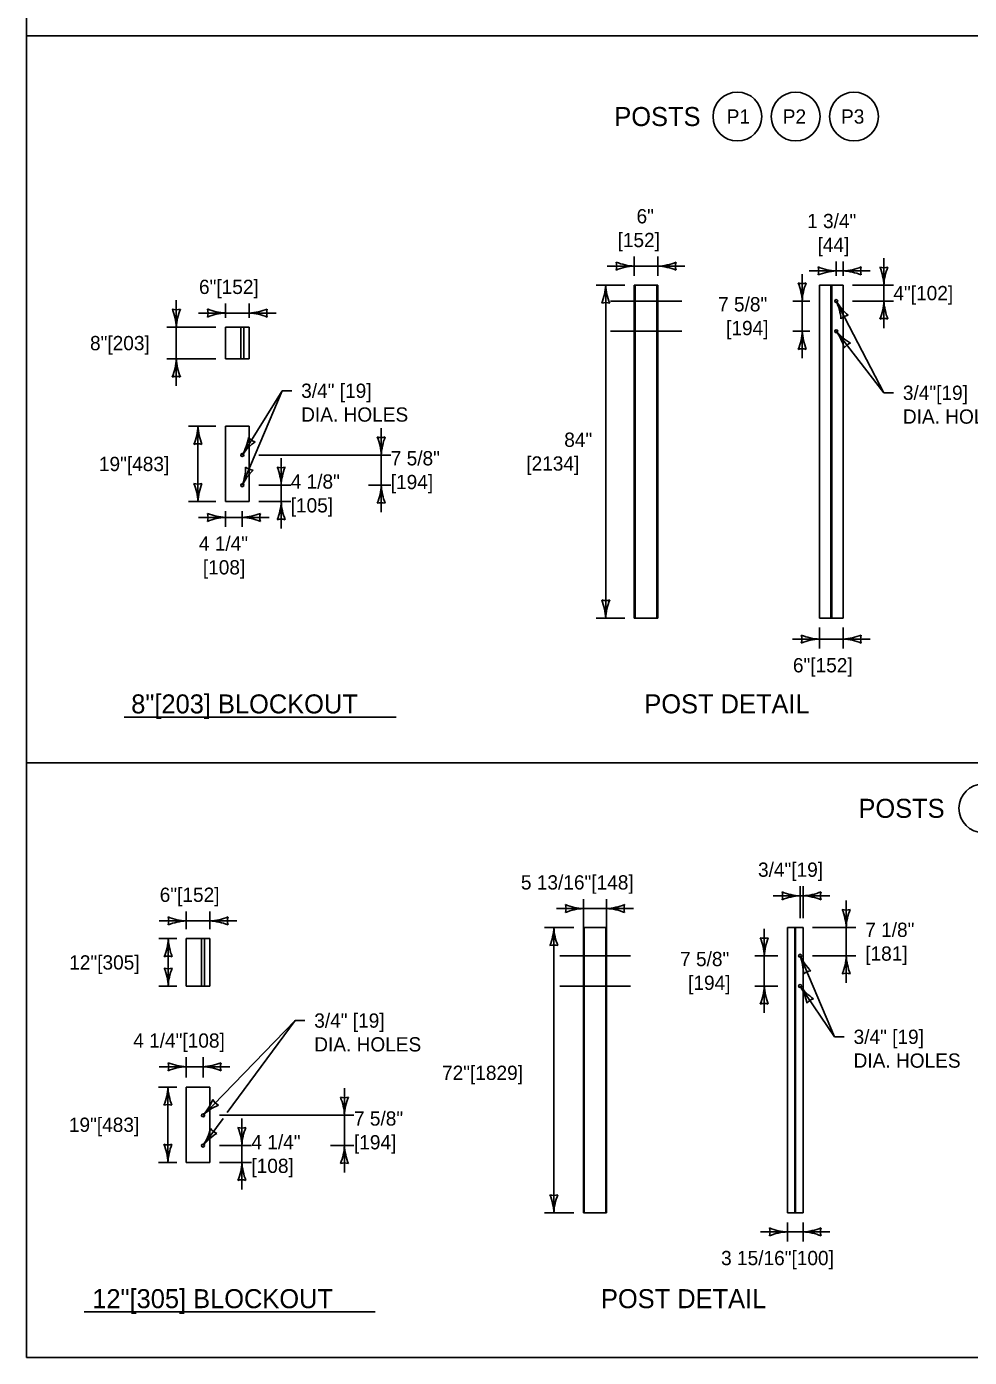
# Model space of a CAD drawing. Extents: x 49991 to 50160, y 49948 to 50051.
# Drawn here: x 49999.38 to 50003.35, y 49987.8 to 49993.4 of the extents above; entities that cross this region are included whole.
import ezdxf

# ---------------------------------------------------------------- set-up
doc = ezdxf.new("R2010")
doc.units = 0
for name, color, linetype in [('Level 1', 7, 'Continuous'), ('Level 2', 7, 'Continuous'), ('Level 3', 7, 'Continuous'), ('Level 4', 7, 'Continuous'), ('Level 5', 7, 'Continuous')]:
    doc.layers.add(name, color=color, linetype=linetype)

msp = doc.modelspace()

# ---------------------------------------------------------------- linework, layer by layer
at = {"layer": 'Level 1'}
for p, q in [((50001.9407, 49990.9086), (50001.9407, 49992.3086)), ((50001.9407, 49992.3086), (50002.0407, 49992.3086)), ((50001.9451, 49990.9086), (50001.9451, 49992.3086)), ((50002.0364, 49990.9086), (50002.0364, 49992.3086)), ((50002.0407, 49990.9086), (50002.0407, 49992.3086)), ((50002.7199, 49990.9086), (50002.7199, 49992.3086)), ((50002.7199, 49992.3086), (50002.8199, 49992.3086)), ((50002.8199, 49990.9086), (50002.8199, 49992.3086)), ((50000.3204, 49992.1316), (50000.2204, 49992.1316)), ((50000.2204, 49991.9983), (50000.2204, 49992.1316)), ((50000.3204, 49991.9983), (50000.3204, 49992.1316)), ((50000.3204, 49991.9983), (50000.2204, 49991.9983)), ((50000.2204, 49991.3984), (50000.2204, 49991.7151)), ((50000.2204, 49991.7151), (50000.3204, 49991.7151)), ((50000.3204, 49991.3984), (50000.3204, 49991.7151)), ((50000.2204, 49991.3984), (50000.3204, 49991.3984)), ((50002.0407, 49990.9086), (50001.9407, 49990.9086)), ((50002.8199, 49990.9086), (50002.7199, 49990.9086)), ((49999.3835, 49990.2991), (50008.2653, 49990.2991)), ((50000.1551, 49989.56), (50000.0551, 49989.56)), ((50000.0551, 49989.56), (50000.0551, 49989.36)), ((50000.1551, 49989.36), (50000.1551, 49989.56)), ((50001.7272, 49989.6067), (50001.7272, 49988.4067)), ((50001.7272, 49989.6067), (50001.8244, 49989.6067)), ((50001.7305, 49989.6067), (50001.7305, 49988.4067)), ((50001.8212, 49989.6067), (50001.8212, 49988.4067)), ((50001.8244, 49989.6067), (50001.8244, 49988.4067)), ((50002.5855, 49989.6067), (50002.6512, 49989.6067)), ((50002.5855, 49989.6067), (50002.5855, 49988.4067)), ((50002.6512, 49989.6067), (50002.6512, 49988.4067)), ((50000.1551, 49989.36), (50000.0551, 49989.36)), ((50000.0551, 49988.619), (50000.0551, 49988.9356)), ((50000.0551, 49988.9356), (50000.1551, 49988.9356)), ((50000.1551, 49988.619), (50000.1551, 49988.9356)), ((50000.0551, 49988.619), (50000.1551, 49988.619)), ((50001.7272, 49988.4067), (50001.8244, 49988.4067)), ((50002.6512, 49988.4067), (50002.5855, 49988.4067))]:
    msp.add_line(p, q, dxfattribs=at)
msp.add_lwpolyline([(49999.3835, 49998.9992), (50016.7501, 49998.9992), (50016.7501, 49987.7988), (49999.3835, 49987.7988)], close=True, dxfattribs=at)
msp.add_lwpolyline([(50006.474, 49990.2991), (50006.474, 49993.358), (49999.3835, 49993.358)], dxfattribs=at)
for centre in [(50002.7908, 49992.2419), (50002.7908, 49992.1149), (50000.2913, 49991.5943), (50000.2913, 49991.4672), (50002.6387, 49989.488), (50002.6387, 49989.3609), (50000.1259, 49988.8169), (50000.126, 49988.6898)]:
    msp.add_circle(centre, 0.00625, dxfattribs=at)
at = {"layer": 'Level 2'}
for p, q in [((49999.7939, 49990.4914), (50000.9385, 49990.4914)), ((49999.6258, 49987.9898), (50000.8504, 49987.9898))]:
    msp.add_line(p, q, dxfattribs=at)
for centre in [(50002.3749, 49993.018), (50002.6202, 49993.018), (50002.8655, 49993.018), (50003.4096, 49990.1082)]:
    msp.add_circle(centre, 0.1026, dxfattribs=at)
at = {"layer": 'Level 3'}
for p, q in [((50001.9407, 49992.3486), (50001.9407, 49992.4286)), ((50002.0407, 49992.3486), (50002.0407, 49992.4286)), ((50002.7908, 49992.3486), (50002.7908, 49992.4086)), ((50002.8199, 49992.3486), (50002.8199, 49992.4086)), ((50002.9914, 49992.422), (50002.9914, 49992.1285)), ((50001.8273, 49992.3886), (50002.1542, 49992.3886)), ((50002.6478, 49992.0014), (50002.6478, 49992.3554)), ((50002.6773, 49992.3686), (50002.9334, 49992.3686)), ((50001.9007, 49992.3086), (50001.7807, 49992.3086)), ((50001.8207, 49992.3086), (50001.8207, 49990.9086)), ((50002.8599, 49992.3086), (50003.0314, 49992.3086)), ((50000.0136, 49991.8849), (50000.0136, 49992.2451)), ((50002.6799, 49992.2419), (50002.6078, 49992.2419)), ((50002.7908, 49992.2419), (50002.9913, 49991.8561)), ((50002.8599, 49992.2419), (50003.0314, 49992.2419)), ((50000.107, 49992.1916), (50000.4339, 49992.1916)), ((50000.2204, 49992.1716), (50000.2204, 49992.2316)), ((50000.3204, 49992.1716), (50000.3204, 49992.2316)), ((50000.1804, 49992.1316), (49999.9736, 49992.1316)), ((50002.6799, 49992.1149), (50002.6078, 49992.1149)), ((50002.7908, 49992.1149), (50002.9913, 49991.8561)), ((50000.1804, 49991.9983), (49999.9736, 49991.9983)), ((50000.2913, 49991.4672), (50000.4591, 49991.8646)), ((50000.2913, 49991.5943), (50000.4591, 49991.8646)), ((50000.4591, 49991.8646), (50000.4991, 49991.8646)), ((50002.9913, 49991.8561), (50003.0313, 49991.8561)), ((50000.1804, 49991.7151), (50000.0646, 49991.7151)), ((50000.1046, 49991.7151), (50000.1046, 49991.3984)), ((50000.876, 49991.7077), (50000.876, 49991.3537)), ((50000.3604, 49991.5942), (50000.916, 49991.5942)), ((50000.4549, 49991.5806), (50000.4549, 49991.285)), ((50000.3604, 49991.4672), (50000.4949, 49991.4672)), ((50000.8217, 49991.4672), (50000.916, 49991.4672)), ((50000.1804, 49991.3984), (50000.0646, 49991.3984)), ((50000.3604, 49991.3984), (50000.4949, 49991.3984)), ((50000.2204, 49991.3584), (50000.2204, 49991.292)), ((50000.2913, 49991.3584), (50000.2913, 49991.292)), ((50000.107, 49991.332), (50000.4047, 49991.332)), ((50000.4549, 49991.3226), (50000.4549, 49991.3027)), ((50001.9007, 49990.9086), (50001.7807, 49990.9086)), ((50002.7199, 49990.8686), (50002.7199, 49990.7801)), ((50002.8199, 49990.8686), (50002.8199, 49990.7801)), ((50002.6065, 49990.8201), (50002.9334, 49990.8201)), ((50002.6387, 49989.6467), (50002.6387, 49989.7802)), ((50002.6512, 49989.6467), (50002.6512, 49989.7802)), ((50001.7272, 49989.6467), (50001.7272, 49989.7267)), ((50001.8244, 49989.6467), (50001.8244, 49989.7267)), ((50002.5253, 49989.7402), (50002.7646, 49989.7402)), ((50002.8329, 49989.7201), (50002.8329, 49989.3745)), ((50000.0551, 49989.6), (50000.0551, 49989.6747)), ((50000.1551, 49989.6), (50000.1551, 49989.6747)), ((50001.6138, 49989.6867), (50001.9378, 49989.6867)), ((50000.2686, 49989.6347), (49999.9417, 49989.6347)), ((50001.7272, 49989.6067), (50001.7272, 49989.6467)), ((50001.8244, 49989.6067), (50001.8244, 49989.6467)), ((50000.0151, 49989.56), (49999.9396, 49989.56)), ((49999.9796, 49989.56), (49999.9796, 49989.36)), ((50001.6872, 49989.6067), (50001.5624, 49989.6067)), ((50001.6024, 49989.6067), (50001.6024, 49988.4067)), ((50002.4879, 49989.2474), (50002.4879, 49989.6014)), ((50002.6912, 49989.6067), (50002.8729, 49989.6067)), ((50002.5455, 49989.488), (50002.4479, 49989.488)), ((50002.6387, 49989.488), (50002.7839, 49989.1472)), ((50002.6912, 49989.488), (50002.8729, 49989.488)), ((50000.0151, 49989.36), (49999.9396, 49989.36)), ((50002.5455, 49989.3609), (50002.4479, 49989.3609)), ((50002.6387, 49989.3609), (50002.7839, 49989.1472)), ((50000.1259, 49988.8169), (50000.514, 49989.2155)), ((50000.2281, 49988.8282), (50000.514, 49989.2155)), ((50000.514, 49989.2155), (50000.554, 49989.2155)), ((50002.7839, 49989.1472), (50002.8239, 49989.1472)), ((50000.0551, 49988.9756), (50000.0551, 49989.0615)), ((50000.1259, 49988.9756), (50000.1259, 49989.0615)), ((49999.9417, 49989.0215), (50000.2394, 49989.0215)), ((50000.0151, 49988.9356), (49999.9382, 49988.9356)), ((49999.9782, 49988.9356), (49999.9782, 49988.619)), ((50000.7212, 49988.9306), (50000.7212, 49988.5766)), ((50000.126, 49988.6898), (50000.2104, 49988.8042)), ((50000.1951, 49988.8171), (50000.7612, 49988.8171)), ((50000.2896, 49988.8035), (50000.2896, 49988.5055)), ((50000.1951, 49988.69), (50000.3296, 49988.69)), ((50000.6619, 49988.69), (50000.7612, 49988.69)), ((50000.0151, 49988.619), (49999.9382, 49988.619)), ((50000.1951, 49988.619), (50000.3296, 49988.619)), ((50000.2896, 49988.5455), (50000.2896, 49988.5055)), ((50001.6872, 49988.4067), (50001.5624, 49988.4067)), ((50002.4721, 49988.3267), (50002.7646, 49988.3267)), ((50002.5855, 49988.3667), (50002.5855, 49988.2867)), ((50002.6512, 49988.3667), (50002.6512, 49988.2867))]:
    msp.add_line(p, q, dxfattribs=at)
for centre, radius, start, end in [((50001.9499, 49992.6111), 0.2223, 247.456, 267.6395), ((50001.8125, 49992.389), 0.0548, 342.1388, 17.8612), ((50001.9522, 49992.1563), 0.233, 92.8273, 112.0772), ((50002.0292, 49992.6213), 0.233, 272.8273, 292.0772), ((50002.0316, 49992.1665), 0.2223, 67.456, 87.6395), ((50002.1689, 49992.3886), 0.0548, 162.1388, 197.8612), ((50002.7999, 49992.5907), 0.2223, 247.456, 267.6395), ((50002.6626, 49992.3686), 0.0548, 342.1388, 17.8612), ((50002.8023, 49992.1359), 0.233, 92.8273, 112.0772), ((50002.8084, 49992.6013), 0.233, 272.8273, 292.0772), ((50002.8108, 49992.1465), 0.2223, 67.456, 87.6395), ((50002.9482, 49992.3686), 0.0548, 162.1388, 197.8612), ((50002.9914, 49992.4368), 0.0548, 252.1388, 287.8612), ((50002.7587, 49992.2971), 0.233, 2.8273, 22.0772), ((50003.2136, 49992.2994), 0.2223, 157.456, 177.6395), ((50001.5986, 49992.3178), 0.2223, 337.456, 357.6395), ((50002.0534, 49992.3201), 0.233, 182.8273, 202.0772), ((50002.6478, 49992.3702), 0.0548, 252.1388, 287.8612), ((50002.415, 49992.2304), 0.233, 2.8273, 22.0772), ((50002.8699, 49992.2328), 0.2223, 157.456, 177.6395), ((50002.5894, 49992.1476), 0.2223, 4.9176, 25.1011), ((50002.992, 49992.3595), 0.233, 210.2889, 229.5388), ((50002.7693, 49992.2511), 0.2223, 337.456, 357.6395), ((50003.2241, 49992.2534), 0.233, 182.8273, 202.0772), ((50000.0136, 49992.2599), 0.0548, 252.1388, 287.8612), ((49999.7809, 49992.1201), 0.233, 2.8273, 22.0772), ((50000.2358, 49992.1225), 0.2223, 157.456, 177.6395), ((50000.2296, 49992.4138), 0.2223, 247.456, 267.6395), ((50000.0922, 49992.1916), 0.0548, 342.1388, 17.8612), ((50000.2319, 49991.9589), 0.233, 92.8273, 112.0772), ((50000.309, 49992.4243), 0.233, 272.8273, 292.0772), ((50000.3113, 49991.9695), 0.2223, 67.456, 87.6395), ((50000.4487, 49992.1916), 0.0548, 162.1388, 197.8612), ((50001.8207, 49992.1804), 0.0548, 72.1388, 107.8612), ((50002.8499, 49992.1282), 0.0548, 99.6004, 135.3228), ((50002.9914, 49992.1137), 0.0548, 72.1388, 107.8612), ((50002.4256, 49992.124), 0.2223, 337.456, 357.6395), ((50002.8805, 49992.1263), 0.233, 182.8273, 202.0772), ((50002.6096, 49991.986), 0.2223, 15.2291, 35.4126), ((50002.9677, 49992.2665), 0.233, 220.6004, 239.8503), ((50002.6478, 49991.9866), 0.0548, 72.1388, 107.8612), ((50002.8693, 49992.0135), 0.0548, 109.9119, 145.6343), ((49999.7915, 49992.0075), 0.2223, 337.456, 357.6395), ((50000.2464, 49992.0098), 0.233, 182.8273, 202.0772), ((50000.0136, 49991.8701), 0.0548, 72.1388, 107.8612), ((49999.8825, 49991.7242), 0.2223, 337.456, 357.6395), ((50000.3373, 49991.7266), 0.233, 182.8273, 202.0772), ((50000.1046, 49991.5869), 0.0548, 72.1388, 107.8612), ((50000.0875, 49991.7072), 0.233, 330.9905, 350.2403), ((50000.4752, 49991.4693), 0.2223, 125.6192, 145.8027), ((50000.3589, 49991.7032), 0.0548, 220.302, 256.0243), ((50000.876, 49991.7225), 0.0548, 252.1388, 287.8612), ((50000.6433, 49991.5828), 0.233, 2.8273, 22.0772), ((50001.0982, 49991.5851), 0.2223, 157.456, 177.6395), ((50000.0724, 49991.5471), 0.233, 339.9296, 359.1794), ((50000.4923, 49991.3723), 0.2223, 134.5583, 154.7418), ((50000.3412, 49991.5853), 0.0548, 229.2411, 264.9634), ((50000.4549, 49991.5954), 0.0548, 252.1388, 287.8612), ((50000.2222, 49991.4557), 0.233, 2.8273, 22.0772), ((50000.677, 49991.458), 0.2223, 157.456, 177.6395), ((50000.1046, 49991.5266), 0.0548, 252.1388, 287.8612), ((49999.8719, 49991.3869), 0.233, 2.8273, 22.0772), ((50000.3268, 49991.3893), 0.2223, 157.456, 177.6395), ((50000.6539, 49991.4763), 0.2223, 337.456, 357.6395), ((50001.1087, 49991.4787), 0.233, 182.8273, 202.0772), ((50000.2328, 49991.4076), 0.2223, 337.456, 357.6395), ((50000.6876, 49991.4099), 0.233, 182.8273, 202.0772), ((50000.2296, 49991.5542), 0.2223, 247.456, 267.6395), ((50000.0922, 49991.332), 0.0548, 342.1388, 17.8612), ((50000.2798, 49991.5647), 0.233, 272.8273, 292.0772), ((50000.4195, 49991.332), 0.0548, 162.1388, 197.8612), ((50000.876, 49991.339), 0.0548, 72.1388, 107.8612), ((50000.2319, 49991.0993), 0.233, 92.8273, 112.0772), ((50000.2821, 49991.1099), 0.2223, 67.456, 87.6395), ((50000.4549, 49991.2702), 0.0548, 72.1388, 107.8612), ((50001.8207, 49991.0368), 0.0548, 252.1388, 287.8612), ((50001.588, 49990.8971), 0.233, 2.8273, 22.0772), ((50002.0429, 49990.8994), 0.2223, 157.456, 177.6395), ((50002.7291, 49991.0422), 0.2223, 247.456, 267.6395), ((50002.5917, 49990.8201), 0.0548, 342.1388, 17.8612), ((50002.7314, 49990.5874), 0.233, 92.8273, 112.0772), ((50002.8084, 49991.0528), 0.233, 272.8273, 292.0772), ((50002.8108, 49990.5979), 0.2223, 67.456, 87.6395), ((50002.9482, 49990.8201), 0.0548, 162.1388, 197.8612), ((50002.6479, 49989.9623), 0.2223, 247.456, 267.6395), ((50002.5105, 49989.7402), 0.0548, 342.1388, 17.8612), ((50002.6502, 49989.5075), 0.233, 92.8273, 112.0772), ((50002.6397, 49989.9729), 0.233, 272.8273, 292.0772), ((50002.642, 49989.5181), 0.2223, 67.456, 87.6395), ((50002.7794, 49989.7402), 0.0548, 162.1388, 197.8612), ((50001.7364, 49989.9088), 0.2223, 247.456, 267.6395), ((50001.599, 49989.6867), 0.0548, 342.1388, 17.8612), ((50001.7387, 49989.454), 0.233, 92.8273, 112.0772), ((50001.8129, 49989.9194), 0.233, 272.8273, 292.0772), ((50001.8152, 49989.4646), 0.2223, 67.456, 87.6395), ((50001.9526, 49989.6867), 0.0548, 162.1388, 197.8612), ((50002.8329, 49989.7349), 0.0548, 252.1388, 287.8612), ((50002.6002, 49989.5952), 0.233, 2.8273, 22.0772), ((50003.055, 49989.5976), 0.2223, 157.456, 177.6395), ((50000.0643, 49989.8568), 0.2223, 247.456, 267.6395), ((49999.9269, 49989.6347), 0.0548, 342.1388, 17.8612), ((50000.0666, 49989.402), 0.233, 92.8273, 112.0772), ((50000.1436, 49989.8674), 0.233, 272.8273, 292.0772), ((50000.146, 49989.4125), 0.2223, 67.456, 87.6395), ((50000.2833, 49989.6347), 0.0548, 162.1388, 197.8612), ((49999.7575, 49989.5691), 0.2223, 337.456, 357.6395), ((50000.2123, 49989.5715), 0.233, 182.8273, 202.0772), ((50001.3803, 49989.6159), 0.2223, 337.456, 357.6395), ((50001.8351, 49989.6182), 0.233, 182.8273, 202.0772), ((50002.4879, 49989.6162), 0.0548, 252.1388, 287.8612), ((50002.2552, 49989.4765), 0.233, 2.8273, 22.0772), ((50002.7101, 49989.4788), 0.2223, 157.456, 177.6395), ((50001.6024, 49989.4785), 0.0548, 72.1388, 107.8612), ((49999.9796, 49989.4318), 0.0548, 72.1388, 107.8612), ((50002.4308, 49989.4093), 0.2223, 0.5366, 20.7201), ((50002.8483, 49989.5898), 0.233, 205.9079, 225.1577), ((50002.6107, 49989.4971), 0.2223, 337.456, 357.6395), ((50003.0656, 49989.4995), 0.233, 182.8273, 202.0772), ((49999.9796, 49989.4882), 0.0548, 252.1388, 287.8612), ((49999.7469, 49989.3485), 0.233, 2.8273, 22.0772), ((50000.2017, 49989.3508), 0.2223, 157.456, 177.6395), ((50002.689, 49989.37), 0.0548, 95.2194, 130.9417), ((50002.8329, 49989.3597), 0.0548, 72.1388, 107.8612), ((50002.2658, 49989.37), 0.2223, 337.456, 357.6395), ((50002.7206, 49989.3724), 0.233, 182.8273, 202.0772), ((50002.4498, 49989.2436), 0.2223, 11.6538, 31.8373), ((50002.8247, 49989.5012), 0.233, 217.0251, 236.2749), ((50002.4879, 49989.2327), 0.0548, 72.1388, 107.8612), ((50002.7108, 49989.2548), 0.0548, 106.3366, 142.0589), ((50000.0643, 49989.2436), 0.2223, 247.4598, 267.6433), ((49999.9269, 49989.0215), 0.0548, 342.1426, 17.865), ((50000.0666, 49988.7888), 0.233, 92.8311, 112.081), ((50000.1144, 49989.2542), 0.233, 272.8311, 292.081), ((50000.1168, 49988.7993), 0.2223, 67.4598, 87.6433), ((50000.2542, 49989.0215), 0.0548, 162.1426, 197.865), ((49999.7561, 49988.9448), 0.2223, 337.456, 357.6395), ((50000.2109, 49988.9471), 0.233, 182.8273, 202.0772), ((49999.9512, 49988.971), 0.233, 318.5917, 337.8415), ((50000.2154, 49988.9088), 0.0548, 207.9032, 243.6255), ((50000.7212, 49988.9454), 0.0548, 252.1388, 287.8612), ((50000.4885, 49988.8056), 0.233, 2.8273, 22.0772), ((50000.9433, 49988.808), 0.2223, 157.456, 177.6395), ((49999.9782, 49988.8074), 0.0548, 72.1388, 107.8612), ((50000.2787, 49988.6554), 0.2223, 113.2204, 133.4039), ((49999.9319, 49988.8188), 0.233, 326.3902, 345.6401), ((50000.2992, 49988.5505), 0.2223, 121.0189, 141.2025), ((50000.2021, 49988.793), 0.0548, 215.7018, 251.4241), ((50000.2896, 49988.8183), 0.0548, 252.1388, 287.8612), ((50000.0569, 49988.6785), 0.233, 2.8273, 22.0772), ((50000.5117, 49988.6809), 0.2223, 157.456, 177.6395), ((49999.9782, 49988.7472), 0.0548, 252.1388, 287.8612), ((49999.7455, 49988.6075), 0.233, 2.8273, 22.0772), ((50000.2004, 49988.6098), 0.2223, 157.456, 177.6395), ((50000.4991, 49988.6992), 0.2223, 337.456, 357.6395), ((50000.9539, 49988.7015), 0.233, 182.8273, 202.0772), ((50000.0674, 49988.6281), 0.2223, 337.456, 357.6395), ((50000.5223, 49988.6305), 0.233, 182.8273, 202.0772), ((50000.7212, 49988.5618), 0.0548, 72.1388, 107.8612), ((50000.2896, 49988.4908), 0.0548, 72.1388, 107.8612), ((50001.6024, 49988.5349), 0.0548, 252.1388, 287.8612), ((50001.3697, 49988.3952), 0.233, 2.8273, 22.0772), ((50001.8246, 49988.3976), 0.2223, 157.456, 177.6395), ((50002.5947, 49988.5488), 0.2223, 247.456, 267.6395), ((50002.4573, 49988.3267), 0.0548, 342.1388, 17.8612), ((50002.597, 49988.094), 0.233, 92.8273, 112.0772), ((50002.6397, 49988.5594), 0.233, 272.8273, 292.0772), ((50002.642, 49988.1046), 0.2223, 67.456, 87.6395), ((50002.7794, 49988.3267), 0.0548, 162.1388, 197.8612)]:
    msp.add_arc(centre, radius, start, end, dxfattribs=at)
at = {"layer": 'Level 4'}
for p, q in [((50002.768, 49992.3086), (50002.768, 49990.9086)), ((50002.7719, 49992.3086), (50002.7719, 49990.9086)), ((50000.285, 49991.9983), (50000.285, 49992.1316)), ((50000.2975, 49991.9983), (50000.2975, 49992.1316)), ((50000.1197, 49989.36), (50000.1197, 49989.56)), ((50000.1322, 49989.36), (50000.1322, 49989.56)), ((50002.617, 49989.6067), (50002.617, 49988.4067)), ((50002.6198, 49989.6067), (50002.6198, 49988.4067))]:
    msp.add_line(p, q, dxfattribs=at)
at = {"layer": 'Level 5'}
for p, q in [((50001.8407, 49992.2419), (50002.1407, 49992.2419)), ((50001.8407, 49992.1149), (50002.1407, 49992.1149)), ((50001.6272, 49989.488), (50001.9244, 49989.488)), ((50001.6272, 49989.3609), (50001.9244, 49989.3609))]:
    msp.add_line(p, q, dxfattribs=at)

# ---------------------------------------------------------------- texts
at = {"layer": 'Level 2'}
for s, height, p in [('POSTS', 0.08, (50001.857, 49992.978)), ('P1', 0.06, (50002.3298, 49992.988)), ('P2', 0.06, (50002.5658, 49992.9881)), ('P3', 0.06, (50002.811, 49992.9881)), ('6"', 0.06, (50001.9504, 49992.5686)), ('1 3/4"', 0.06, (50002.6683, 49992.5486)), ('[152]', 0.06, (50001.8705, 49992.4686)), ('[44]', 0.06, (50002.7121, 49992.4486)), ('6"[152]', 0.06, (50000.109, 49992.2716)), ('4"[102]', 0.06, (50003.0314, 49992.2453)), ('7 5/8"', 0.06, (50002.2936, 49992.1984)), ('[194]', 0.06, (50002.3273, 49992.0984)), ('8"[203]', 0.06, (49999.6503, 49992.035)), ('3/4" [19]', 0.06, (50000.5391, 49991.8346)), ('3/4"[19]', 0.06, (50003.0713, 49991.8261)), ('DIA. HOLES', 0.06, (50000.5391, 49991.7346)), ('DIA. HOLES', 0.06, (50003.0713, 49991.7261)), ('84"', 0.06, (50001.6462, 49991.6286)), ('19"[483]', 0.06, (49999.6878, 49991.5267)), ('7 5/8"', 0.06, (50000.916, 49991.5507)), ('[2134]', 0.06, (50001.4864, 49991.5286)), ('4 1/8"', 0.06, (50000.4949, 49991.4528)), ('[194]', 0.06, (50000.916, 49991.4507)), ('[105]', 0.06, (50000.4949, 49991.3528)), ('4 1/4"', 0.06, (50000.1084, 49991.192)), ('[108]', 0.06, (50000.1252, 49991.092)), ('6"[152]', 0.06, (50002.6085, 49990.6801)), ('8"[203] BLOCKOUT', 0.08, (49999.8238, 49990.5074)), ('POST DETAIL', 0.08, (50001.9833, 49990.5077)), ('POSTS', 0.08, (50002.8843, 49990.0682)), ('3/4"[19]', 0.06, (50002.4617, 49989.8202)), ('6"[152]', 0.06, (49999.9437, 49989.7147)), ('5 13/16"[148]', 0.06, (50001.4638, 49989.7667)), ('7 1/8"', 0.06, (50002.9129, 49989.5673)), ('7 5/8"', 0.06, (50002.1338, 49989.4444)), ('[181]', 0.06, (50002.9129, 49989.4673)), ('12"[305]', 0.06, (49999.5628, 49989.43)), ('[194]', 0.06, (50002.1675, 49989.3444)), ('3/4" [19]', 0.06, (50000.594, 49989.1855)), ('4 1/4"[108]', 0.06, (49999.8323, 49989.1015)), ('3/4" [19]', 0.06, (50002.8639, 49989.1172)), ('DIA. HOLES', 0.06, (50000.594, 49989.0855)), ('DIA. HOLES', 0.06, (50002.8639, 49989.0172)), ('72"[1829]', 0.06, (50001.1318, 49988.9658)), ('7 5/8"', 0.06, (50000.7612, 49988.7736)), ('19"[483]', 0.06, (49999.5614, 49988.7473)), ('4 1/4"', 0.06, (50000.3296, 49988.6745)), ('[194]', 0.06, (50000.7612, 49988.6736)), ('[108]', 0.06, (50000.3296, 49988.5745)), ('3 15/16"[100]', 0.06, (50002.3063, 49988.1867)), ('12"[305] BLOCKOUT', 0.08, (49999.6598, 49988.0058)), ('POST DETAIL', 0.08, (50001.8008, 49988.0058))]:
    msp.add_text(s, height=height, dxfattribs=at).set_placement(p)

doc.saveas('drawing.dxf')
